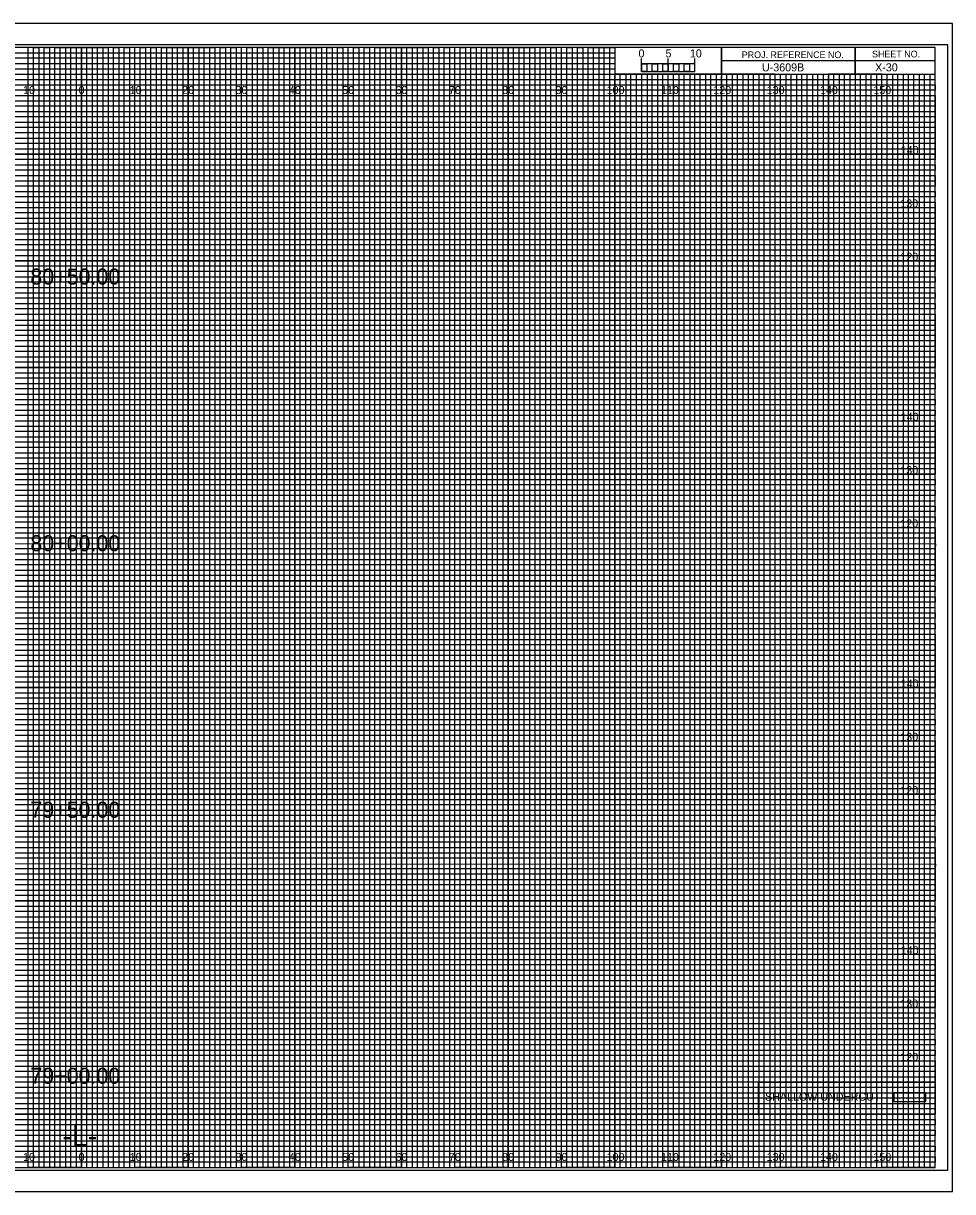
# Model space of a CAD drawing. Extents: x -13 to 329, y -17 to 10994.
# Drawn here: x 149.1 to 323.3, y 6155.5 to 6374.5 of the extents above; entities that cross this region are included whole.
import ezdxf

# ---------------------------------------------------------------- set-up
doc = ezdxf.new("R2010")
doc.units = 0
for name, color, linetype in [('Prop DSN Text', 7, 'Continuous'), ('Prop Grid Mask', 7, 'Continuous'), ('Prop Road Plan_ Recs - UC Shallow (pattern)', 7, 'Continuous'), ('Prop XS Alignment Label', 7, 'Continuous'), ('Prop XS Bar Scale Labels', 7, 'Continuous'), ('Prop XS Elevation Labels', 7, 'Continuous'), ('Prop XS Offset Labels', 7, 'Continuous'), ('Prop XS Project Number', 7, 'Continuous'), ('Prop XS Sheet Number', 7, 'Continuous'), ('Prop XS Station Labels', 7, 'Continuous'), ('Sheet Cross Section CELL', 7, 'Continuous'), ('Sheet Cross Section Grid Major CELL', 7, 'Continuous'), ('Sheet Cross Section Grid Middle CELL', 7, 'Continuous'), ('Sheet Cross Section Grid Minor 1 CELL', 7, 'Continuous'), ('Sheet Cross Section Grid Minor 2 CELL', 7, 'Continuous'), ('Sheet Cross Section Scale CELL', 7, 'Continuous'), ('Sheet Cutting Line CELL', 7, 'Continuous'), ('Sheet DOT Grid CELL', 7, 'Continuous'), ('Sheet Plot Border Inside CELL', 7, 'Continuous'), ('Sheet Plot Border Outside CELL', 7, 'Continuous')]:
    doc.layers.add(name, color=color, linetype=linetype)

msp = doc.modelspace()

# ---------------------------------------------------------------- linework, layer by layer
at = {"layer": 'Prop Grid Mask'}
msp.add_lwpolyline([(286.89, 6176.03), (320, 6176.03), (320, 6170), (286.89, 6170)], close=True, dxfattribs=at)
at = {"layer": 'Prop Road Plan_ Recs - UC Shallow (pattern)'}
msp.add_lwpolyline([(312.34, 6174.08), (318.23, 6174.08), (318.23, 6172.36), (312.34, 6172.36)], close=True, dxfattribs=at)
at = {"layer": 'Sheet Cross Section CELL'}
for p, q in [((305, 6370), (305, 6365)), ((305, 6365), (305, 6370)), ((280, 6367.5), (280, 6365)), ((320, 6367.49), (280, 6367.49)), ((280, 6365), (320, 6365))]:
    msp.add_line(p, q, dxfattribs=at)
for points in [[(320, 6370), (0, 6370), (0, 6160), (320, 6160)], [(280, 6370), (260, 6370), (260, 6365.03), (280, 6365.03)], [(320, 6370), (280, 6370), (280, 6365), (320, 6365)]]:
    msp.add_lwpolyline(points, close=True, dxfattribs=at)
at = {"layer": 'Sheet Cross Section Grid Major CELL'}
for p, q in [((150, 6370), (140, 6370)), ((150, 6160), (150, 6370)), ((170, 6370), (160, 6370)), ((160, 6370), (160, 6160)), ((170, 6160), (170, 6370)), ((190, 6370), (180, 6370)), ((180, 6370), (180, 6160)), ((190, 6160), (190, 6370)), ((210, 6370), (200, 6370)), ((200, 6370), (200, 6160)), ((210, 6160), (210, 6370)), ((230, 6370), (220, 6370)), ((220, 6370), (220, 6160)), ((230, 6160), (230, 6370)), ((250, 6370), (240, 6370)), ((240, 6370), (240, 6160)), ((250, 6160), (250, 6370)), ((260, 6370), (260, 6160)), ((270, 6160), (270, 6365)), ((290, 6365), (280, 6365)), ((280, 6365), (280, 6160)), ((290, 6160), (290, 6365)), ((310, 6365), (300, 6365)), ((300, 6365), (300, 6160)), ((310, 6160), (310, 6365)), ((160, 6160), (150, 6160)), ((180, 6160), (170, 6160)), ((200, 6160), (190, 6160)), ((220, 6160), (210, 6160)), ((240, 6160), (230, 6160)), ((260, 6160), (250, 6160)), ((280, 6160), (270, 6160)), ((300, 6160), (290, 6160)), ((320, 6160), (310, 6160)), ((320, 6160), (320, 6160))]:
    msp.add_line(p, q, dxfattribs=at)
for points in [[(0, 6360), (320, 6360), (320, 6350), (0, 6350)], [(0, 6340), (320, 6340), (320, 6330), (0, 6330)], [(0, 6320), (320, 6320), (320, 6310), (0, 6310)], [(0, 6300), (320, 6300), (320, 6290), (0, 6290)], [(0, 6280), (320, 6280), (320, 6270), (0, 6270)], [(0, 6260), (320, 6260), (320, 6250), (0, 6250)], [(0, 6240), (320, 6240), (320, 6230), (0, 6230)], [(0, 6220), (320, 6220), (320, 6210), (0, 6210)], [(0, 6200), (320, 6200), (320, 6190), (0, 6190)], [(0, 6180), (320, 6180), (320, 6170), (0, 6170)]]:
    msp.add_lwpolyline(points, dxfattribs=at)
at = {"layer": 'Sheet Cross Section Grid Middle CELL'}
for points in [[(145, 6160), (155, 6160), (155, 6370), (165, 6370), (165, 6160), (175, 6160), (175, 6370), (185, 6370), (185, 6160), (195, 6160), (195, 6370), (205, 6370), (205, 6160), (215, 6160), (215, 6370), (225, 6370), (225, 6160), (235, 6160), (235, 6370), (245, 6370), (245, 6160), (255, 6160), (255, 6370), (259.93, 6370), (260, 6370), (260, 6365), (264.99, 6365), (264.99, 6160), (275, 6160), (275, 6365), (285, 6365), (285, 6160), (295, 6160), (295, 6365), (305, 6365), (305, 6160), (315, 6160), (315, 6365)], [(0, 6365), (275, 6365)], [(0, 6345), (320, 6345), (320, 6355), (0, 6355)], [(0, 6325), (320, 6325), (320, 6335), (0, 6335)], [(0, 6305), (320, 6305), (320, 6315), (0, 6315)], [(0, 6285), (320, 6285), (320, 6295), (0, 6295)], [(0, 6265), (320, 6265), (320, 6275), (0, 6275)], [(0, 6245), (320, 6245), (320, 6255), (0, 6255)], [(0, 6225), (320, 6225), (320, 6235), (0, 6235)], [(0, 6205), (320, 6205), (320, 6215), (0, 6215)], [(0, 6185), (320, 6185), (320, 6195), (0, 6195)], [(0, 6165), (320, 6165), (320, 6175), (0, 6175)]]:
    msp.add_lwpolyline(points, dxfattribs=at)
at = {"layer": 'Sheet Cross Section Grid Minor 1 CELL'}
for p, q in [((0, 6369), (260, 6369)), ((260, 6369), (260, 6367.98)), ((260, 6367.98), (0, 6367.98)), ((0, 6367), (260, 6367)), ((260, 6367), (260, 6365.89)), ((260, 6365.89), (0, 6365.89)), ((0, 6364), (320, 6364))]:
    msp.add_line(p, q, dxfattribs=at)
for points in [[(0, 6363), (270, 6363), (320, 6363), (320, 6362), (0, 6362)], [(0, 6361), (320, 6361), (320, 6359), (0, 6359)], [(0, 6358), (320, 6358), (320, 6357), (0, 6356.98)], [(0, 6356), (320, 6356), (320, 6354), (0, 6354)], [(0, 6353), (320, 6353), (320, 6352), (0, 6352)], [(0, 6351), (320, 6351), (320, 6349), (0, 6349)], [(0, 6348), (320, 6348), (320, 6347), (0, 6347)], [(0, 6346), (320, 6346), (320, 6344), (0, 6344)], [(0, 6343), (320, 6343), (320, 6342), (0, 6342)], [(0, 6341), (320, 6341), (320, 6339), (0, 6339)], [(0, 6338), (320, 6338), (320, 6337), (0, 6337)], [(0, 6336), (320, 6336), (320, 6333.95), (320, 6333), (320, 6332), (0, 6332)], [(0, 6334), (320, 6334), (320, 6333), (0, 6333)], [(0, 6331), (320, 6331), (320, 6329), (0, 6329.03)], [(0, 6329.03), (320, 6329), (320, 6328), (0, 6328)], [(0, 6327), (320, 6327), (320, 6326), (0, 6326)], [(0, 6324), (320, 6324), (320, 6323), (0, 6323)], [(0, 6322), (320, 6322), (320, 6321), (0, 6321)], [(-0.07, 6318.89), (320, 6318.89), (320, 6317.88), (-0.07, 6317.88)], [(0, 6317), (320, 6317), (320, 6316), (0, 6316)], [(0, 6314), (320, 6314), (320, 6313), (0, 6313)], [(0, 6312), (320, 6312), (320, 6311), (0, 6311)], [(0, 6309), (320, 6309), (320, 6308), (0, 6308)], [(0, 6307), (320, 6307), (320, 6306), (0, 6306)], [(0, 6304), (320, 6304), (320, 6303), (0, 6303)], [(0, 6302), (320, 6302), (320, 6301), (0, 6301)], [(0, 6299), (320, 6299), (319.99, 6297.98), (0, 6298)], [(0, 6297), (320, 6297), (320, 6296), (0, 6296)], [(0, 6294), (320, 6294), (320, 6293), (0, 6293)], [(0, 6292), (320, 6292), (320, 6291), (0, 6291)], [(0, 6289), (320, 6289), (320, 6288), (0, 6288)], [(0, 6287), (320, 6287), (320, 6286), (0, 6286)], [(0, 6284), (320, 6284), (320, 6283), (0, 6283)], [(0, 6282), (320, 6282), (320, 6281), (0, 6281)], [(0, 6279), (320, 6279), (320, 6278), (0, 6278)], [(0, 6276.99), (320.07, 6276.91), (320, 6276), (0, 6276)], [(0, 6274), (320, 6274), (320, 6273), (0, 6273)], [(0, 6272), (320, 6272), (320, 6271), (0, 6271)], [(0, 6269), (320, 6269), (320, 6268), (0, 6268)], [(0, 6267), (320, 6267), (320, 6266), (0, 6266)], [(0, 6264), (320, 6264), (320, 6263), (0, 6263)], [(0, 6262), (320, 6262), (320, 6261), (0, 6261)], [(0, 6259), (320, 6259), (320, 6258), (0, 6258)], [(0, 6257), (320, 6257), (320, 6256), (0, 6256)], [(0, 6254), (320, 6254), (320, 6253), (0, 6253)], [(0, 6252), (320, 6252), (320, 6251), (0, 6251)], [(0, 6249), (320, 6249), (320, 6248), (0, 6248)], [(0, 6247), (320, 6247), (320, 6246), (0, 6246)], [(0, 6244), (320, 6244), (320, 6243), (0, 6243)], [(0, 6242), (320, 6242), (320, 6241), (0, 6241)], [(0, 6239), (320, 6239), (319.99, 6237.98), (0, 6238)], [(0, 6237), (320, 6237), (320, 6236), (0, 6236)], [(0, 6234), (320, 6234), (320, 6233), (0, 6233)], [(0, 6232), (320, 6232), (320, 6231), (0, 6231)], [(0, 6229), (320, 6229), (320, 6228), (0, 6228)], [(0, 6227), (320, 6227), (320, 6226), (0, 6226)], [(0, 6224), (320, 6224), (320, 6223), (0, 6223)], [(0, 6222), (320, 6222), (320, 6221), (0, 6221)], [(0, 6219), (320, 6219), (320, 6218), (0, 6218)], [(0, 6216.99), (320.07, 6216.91), (320, 6216), (0, 6216)], [(0, 6214), (320, 6214), (320, 6213), (0, 6213)], [(0, 6212), (320, 6212), (320, 6211), (0, 6211)], [(0, 6209), (320, 6209), (320, 6208), (0, 6208)], [(0, 6207), (320, 6207), (320, 6206), (0, 6206)], [(0, 6204), (320, 6204), (320, 6203), (0, 6203)], [(0, 6202), (320, 6202), (320, 6201), (0, 6201)], [(0, 6199), (320, 6199), (320, 6198), (0, 6198)], [(0, 6197), (320, 6197), (320, 6196), (0, 6196)], [(0, 6194), (320, 6194), (320, 6193), (0, 6193)], [(0, 6192), (320, 6192), (320, 6191), (0, 6191)], [(0, 6189), (320, 6189), (320, 6188), (0, 6188)], [(0, 6187), (320, 6187), (320, 6186), (0, 6186)], [(0, 6184), (320, 6184), (320, 6183), (0, 6183)], [(0, 6182), (320, 6182), (320, 6181), (0, 6181)], [(0, 6179), (320, 6179), (320, 6178), (0, 6178)], [(0, 6177), (320, 6177), (320, 6176), (0, 6176)], [(0, 6174), (320, 6174), (320, 6173), (0, 6173)], [(0, 6172), (320, 6172), (320, 6171), (0, 6171)], [(0, 6169), (320, 6169), (320, 6168), (0, 6168)], [(0, 6167), (320, 6167), (320, 6166), (0, 6166)], [(0, 6164), (320, 6164), (320, 6163), (0, 6163)], [(0, 6162), (320, 6162), (320, 6161), (0, 6161)]]:
    msp.add_lwpolyline(points, dxfattribs=at)
at = {"layer": 'Sheet Cross Section Grid Minor 2 CELL'}
for p, q in [((267, 6365), (266.01, 6365)), ((266.01, 6365), (266.01, 6160)), ((267, 6160), (267, 6365)), ((269, 6365), (268, 6365)), ((268, 6365), (268, 6160)), ((269, 6160), (269, 6365)), ((266.01, 6160), (265, 6160)), ((268, 6160), (267, 6160))]:
    msp.add_line(p, q, dxfattribs=at)
for points in [[(150, 6160), (151, 6160), (151, 6370), (152, 6370), (152, 6160)], [(152, 6160), (153, 6160), (153, 6370), (154, 6370), (154, 6160)], [(155, 6160), (156, 6160), (156, 6370), (157, 6370), (157, 6160)], [(157, 6160), (158, 6160), (158, 6370), (159, 6370), (159, 6160)], [(160, 6160), (161, 6160), (161, 6370), (162, 6370), (162, 6160)], [(162, 6160), (163, 6160), (163, 6370), (164, 6370), (164, 6160)], [(165, 6160), (166, 6160), (166, 6370), (167, 6370), (167, 6160)], [(167, 6160), (168, 6160), (168, 6370), (169, 6370), (169, 6160)], [(170, 6160), (171, 6160), (171, 6370), (172, 6370), (172, 6160)], [(172, 6160), (173, 6160), (173, 6370), (174, 6370), (174, 6160)], [(175, 6160), (176, 6160), (176, 6370), (177, 6370), (177, 6160)], [(177, 6160), (178, 6160), (178, 6370), (179, 6370), (179, 6160)], [(180, 6160), (181, 6160), (181, 6370), (182, 6370), (182, 6160)], [(182, 6160), (183, 6160), (183, 6370), (184, 6370), (184, 6160)], [(185, 6160), (186, 6160), (186, 6370), (187, 6370), (187, 6160)], [(187, 6160), (188, 6160), (188, 6370), (189, 6370), (189, 6160)], [(190, 6160), (191, 6160), (191, 6370), (192, 6370), (192, 6160)], [(192, 6160), (193, 6160), (193, 6370), (194, 6370), (194, 6160)], [(195, 6160), (196, 6160), (196, 6370), (197, 6370), (197, 6160)], [(197, 6160), (198, 6160), (198, 6370), (199, 6370), (199, 6160)], [(200, 6160), (201, 6160), (201, 6370), (202, 6370), (202, 6160)], [(202, 6160), (203, 6160), (203, 6370), (204, 6370), (204, 6160)], [(205, 6160), (206, 6160), (206, 6370), (207, 6370), (207, 6160)], [(207, 6160), (208, 6160), (208, 6370), (209, 6370), (209, 6160)], [(210, 6160), (211, 6160), (211, 6370), (212, 6370), (212, 6160)], [(212, 6160), (213, 6160), (213, 6370), (214, 6370), (214, 6160)], [(215, 6160), (216, 6160), (216, 6370), (217, 6370), (217, 6160)], [(217, 6160), (218, 6160), (218, 6370), (219, 6370), (219, 6160)], [(220, 6160), (221, 6160), (221, 6370), (222, 6370), (222, 6160)], [(222, 6160), (223, 6160), (223, 6370), (224, 6370), (224, 6160)], [(225, 6160), (226, 6160), (226, 6370), (227, 6370), (227, 6160)], [(227, 6160), (228, 6160), (228, 6370), (229, 6370), (229, 6160)], [(230, 6160), (231, 6160), (231, 6370), (232, 6370), (232, 6160)], [(232, 6160), (233, 6160), (233, 6370), (234, 6370), (234, 6160)], [(235, 6160), (236, 6160), (236, 6370), (237, 6370), (237, 6160)], [(237, 6160), (238, 6160), (238, 6370), (239, 6370), (239, 6160)], [(240, 6160), (241, 6160), (241, 6370), (242, 6370), (242, 6160)], [(242, 6160), (243, 6160), (243, 6370), (244, 6370), (244, 6160)], [(245, 6160), (246, 6160), (246, 6370), (247, 6370), (247, 6160)], [(247, 6160), (248, 6160), (248, 6370), (249, 6370), (249, 6160)], [(250, 6160), (251, 6160), (251, 6370), (252, 6370), (252, 6160)], [(252, 6160), (253, 6160), (253, 6370), (254, 6370), (254, 6160)], [(255, 6160), (256, 6160), (256, 6370), (257, 6370), (257, 6160)], [(257, 6160), (258, 6160), (258, 6370), (259, 6370), (259, 6160)], [(260, 6160), (261, 6160), (261, 6365), (262.02, 6365), (262.02, 6160)], [(262, 6160), (263, 6160), (263, 6365), (263.99, 6365), (263.99, 6160)], [(270, 6160), (270.98, 6160), (270.98, 6365), (272, 6365), (272, 6160)], [(272, 6160), (273, 6160), (273, 6365), (274.05, 6365), (274.05, 6160)], [(275, 6160), (276, 6160), (276, 6365), (277, 6365), (277, 6160)], [(277, 6160), (278, 6160), (278, 6365), (279, 6365), (279, 6160)], [(280, 6160), (281, 6160), (281, 6365), (282, 6365), (282, 6160)], [(282, 6160), (283, 6160), (283, 6365), (284, 6365), (284, 6160)], [(285, 6160), (286, 6160), (286, 6365), (287, 6365), (287, 6160)], [(287, 6160), (288, 6160), (288, 6365), (289, 6365), (289, 6160)], [(290, 6160), (291, 6160), (291, 6365), (292, 6365), (292, 6160)], [(292, 6160), (293, 6160), (293, 6365), (294, 6365), (294, 6160)], [(295, 6160), (296, 6160), (296, 6365), (297, 6365), (297, 6160)], [(297, 6160), (298, 6160), (298, 6365), (299, 6365), (299, 6160)], [(300, 6160), (301, 6160), (301, 6365), (302, 6365), (302, 6160)], [(302, 6160), (303, 6160), (303, 6365), (304, 6365), (304, 6160)], [(305, 6160), (306, 6160), (306, 6365), (307, 6365), (307, 6160)], [(307, 6160), (308, 6160), (308, 6365), (309, 6365), (309, 6160)], [(310, 6160), (311, 6160), (311, 6365), (312, 6365), (312, 6160)], [(312, 6160), (313, 6160), (313, 6365), (314, 6365), (314, 6160)], [(315, 6160), (316, 6160), (316, 6365), (317, 6365), (317, 6160)], [(317, 6160), (318, 6160), (318, 6365), (319, 6365), (319, 6160)]]:
    msp.add_lwpolyline(points, dxfattribs=at)
at = {"layer": 'Sheet Cross Section Scale CELL'}
for p, q in [((265, 6365.49), (265, 6367.9)), ((265, 6366.9), (265, 6367.9)), ((270, 6365.49), (270, 6367.9)), ((275, 6365.49), (275, 6367.9)), ((275, 6366.9), (275, 6367.9))]:
    msp.add_line(p, q, dxfattribs=at)
for points in [[(275, 6366.9), (265, 6366.9), (265, 6365.49), (275, 6365.49)], [(265, 6366.9), (266, 6366.9), (266, 6365.49), (265, 6365.49)], [(267, 6366.9), (268, 6366.9), (268, 6365.49), (267, 6365.49)], [(269, 6366.9), (270, 6366.9), (270, 6365.49), (269, 6365.49)], [(271, 6366.9), (272, 6366.9), (272, 6365.49), (271, 6365.49)], [(273, 6366.9), (274, 6366.9), (274, 6365.49), (273, 6365.49)]]:
    msp.add_lwpolyline(points, close=True, dxfattribs=at)
at = {"layer": 'Sheet Cutting Line CELL'}
for p, q in [((323.3, 6374.5), (-13.4, 6374.5)), ((-13.4, 6155.5), (323.3, 6155.5))]:
    msp.add_line(p, q, dxfattribs=at)
at = {"layer": 'Sheet DOT Grid CELL'}
for p, q in [((150, 6160), (150, 6370)), ((160, 6160), (160, 6370)), ((170, 6160), (170, 6370)), ((180, 6160), (180, 6370)), ((190, 6160), (190, 6370)), ((200, 6160), (200, 6370)), ((210, 6160), (210, 6370)), ((220, 6160), (220, 6370)), ((230, 6160), (230, 6370)), ((240, 6160), (240, 6370)), ((250, 6160), (250, 6370)), ((260, 6160), (260, 6364.69)), ((270, 6160), (270, 6364.69)), ((280, 6160), (280, 6364.69)), ((290, 6160), (290, 6364.69)), ((300, 6160), (300, 6364.69)), ((310, 6160), (310, 6364.69)), ((0, 6360), (320, 6360)), ((0, 6350), (320, 6350)), ((0, 6340), (320, 6340)), ((0, 6330), (320, 6330)), ((0, 6320), (320, 6320)), ((0, 6310), (320, 6310)), ((0, 6300), (320, 6300)), ((0, 6290), (320, 6290)), ((0, 6280), (320, 6280)), ((0, 6270), (320, 6270)), ((0, 6260), (320, 6260)), ((0, 6250), (320, 6250)), ((0, 6240), (320, 6240)), ((0, 6230), (320, 6230)), ((0, 6220), (320, 6220)), ((0, 6210), (320, 6210)), ((0, 6200), (320, 6200)), ((0, 6190), (320, 6190)), ((0, 6180), (320, 6180)), ((0, 6170), (320, 6170))]:
    msp.add_line(p, q, dxfattribs=at)
at = {"layer": 'Sheet Plot Border Inside CELL'}
msp.add_lwpolyline([(-10.8, 6159.5), (322.4, 6159.5), (322.4, 6370.5), (-10.8, 6370.5)], close=True, dxfattribs=at)
at = {"layer": 'Sheet Plot Border Outside CELL'}
msp.add_lwpolyline([(-13.4, 6155.5), (323.3, 6155.5), (323.3, 6374.5), (-13.4, 6374.5)], close=True, dxfattribs=at)

# ---------------------------------------------------------------- texts
at = {"layer": 'Prop DSN Text'}
msp.add_text('SHALLOW UNDERCUT', height=1.5, dxfattribs=at).set_placement((288.13, 6172.55))
at = {"layer": 'Prop XS Alignment Label'}
msp.add_text('-L-', height=4, dxfattribs=at).set_placement((156.42, 6164))
at = {"layer": 'Prop XS Bar Scale Labels'}
for s, p in [('5', (269.47, 6368.12)), ('10', (274.04, 6368.12))]:
    msp.add_text(s, height=1.5, dxfattribs=at).set_placement(p)
at = {"layer": 'Prop XS Elevation Labels'}
for s, p in [('140', (313.57, 6350)), ('130', (313.49, 6340)), ('120', (313.5, 6330)), ('140', (313.57, 6300)), ('130', (313.49, 6290)), ('120', (313.5, 6280)), ('140', (313.57, 6250)), ('130', (313.49, 6240)), ('120', (313.5, 6230)), ('140', (313.57, 6200)), ('130', (313.49, 6190)), ('120', (313.5, 6180))]:
    msp.add_text(s, height=1.5, dxfattribs=at).set_placement(p)
at = {"layer": 'Prop XS Offset Labels'}
for s, p in [('10', (149.04, 6361.25)), ('0', (159.45, 6361.25)), ('0', (159.45, 6361.25)), ('10', (169.04, 6361.25)), ('20', (178.86, 6361.25)), ('30', (188.86, 6361.25)), ('40', (198.86, 6361.25)), ('50', (208.86, 6361.25)), ('60', (218.86, 6361.25)), ('70', (228.86, 6361.25)), ('80', (238.86, 6361.25)), ('90', (248.86, 6361.25)), ('100', (258.44, 6361.25)), ('110', (268.62, 6361.25)), ('120', (278.44, 6361.25)), ('130', (288.44, 6361.25)), ('140', (298.44, 6361.25)), ('150', (308.44, 6361.25)), ('10', (149.04, 6161.25)), ('0', (159.45, 6161.25)), ('0', (159.45, 6161.25)), ('10', (169.04, 6161.25)), ('20', (178.86, 6161.25)), ('30', (188.86, 6161.25)), ('40', (198.86, 6161.25)), ('50', (208.86, 6161.25)), ('60', (218.86, 6161.25)), ('70', (228.86, 6161.25)), ('80', (238.86, 6161.25)), ('90', (248.86, 6161.25)), ('100', (258.44, 6161.25)), ('110', (268.62, 6161.25)), ('120', (278.44, 6161.25)), ('130', (288.44, 6161.25)), ('140', (298.44, 6161.25)), ('150', (308.44, 6161.25))]:
    msp.add_text(s, height=1.5, dxfattribs=at).set_placement(p)
at = {"layer": 'Prop XS Project Number'}
msp.add_text('U-3609B', height=1.5, dxfattribs=at).set_placement((287.56, 6365.5))
at = {"layer": 'Prop XS Sheet Number'}
msp.add_text('X-30', height=1.5, dxfattribs=at).set_placement((308.77, 6365.5))
at = {"layer": 'Prop XS Station Labels'}
for s, p in [('80+50.00', (150.41, 6325.54)), ('80+00.00', (150.41, 6275.55)), ('79+50.00', (150.41, 6225.59)), ('79+00.00', (150.41, 6175.72))]:
    msp.add_text(s, height=3, dxfattribs=at).set_placement(p)
at = {"layer": 'Sheet Cross Section CELL'}
for s, p in [('PROJ. REFERENCE NO.', (283.77, 6367.99)), ('SHEET NO.', (308.19, 6368.12))]:
    msp.add_text(s, height=1.25, dxfattribs=at).set_placement(p)
at = {"layer": 'Sheet Cross Section Scale CELL'}
msp.add_text('0', height=1.5, dxfattribs=at).set_placement((264.41, 6368.12))

doc.saveas('drawing.dxf')
